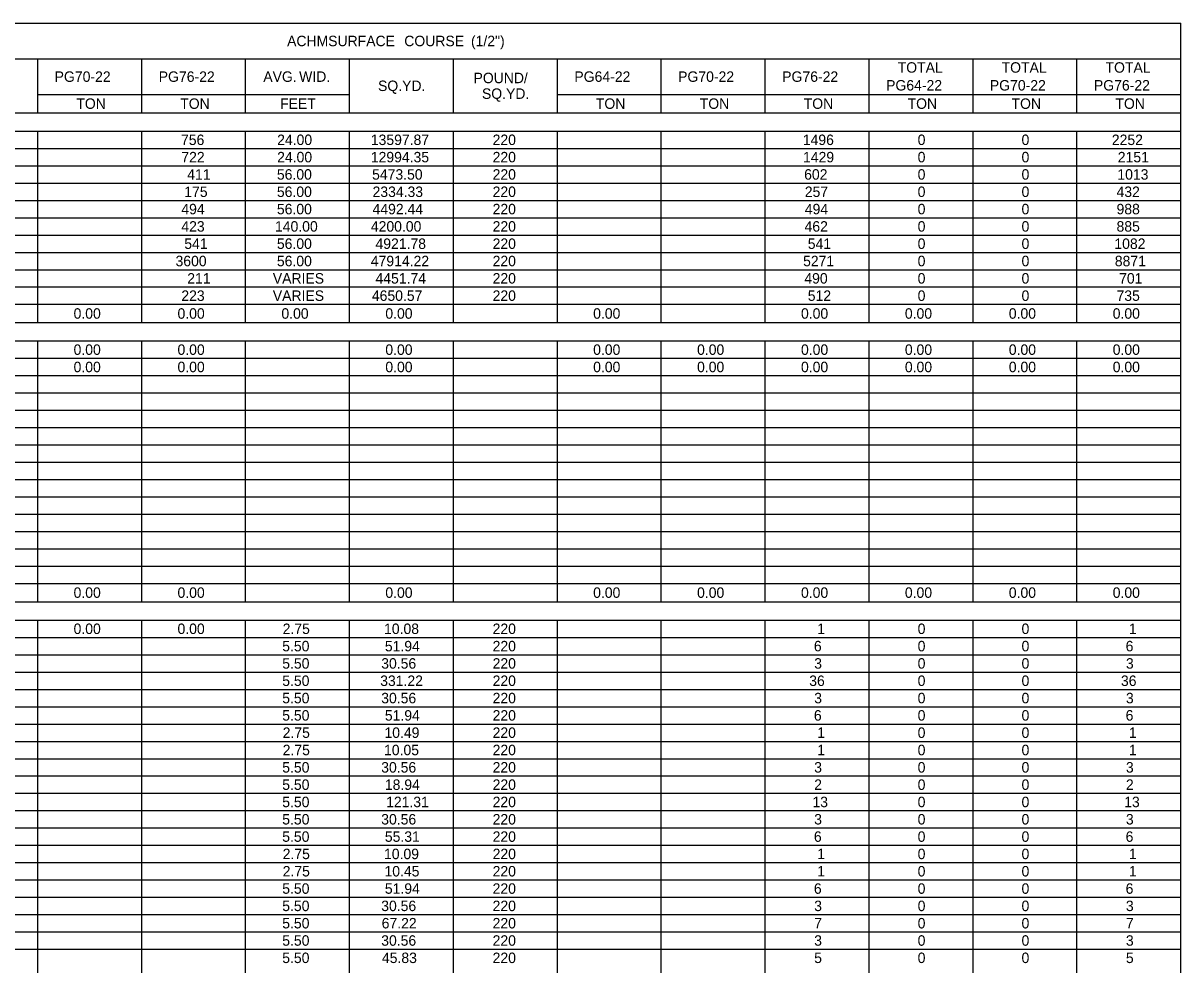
# Model space of a CAD drawing. Extents: x 1226590 to 1228573, y 151304 to 154224.
# Drawn here: x 1228019 to 1228573, y 153764 to 154214 of the extents above; entities that cross this region are included whole.
import ezdxf

# ---------------------------------------------------------------- set-up
doc = ezdxf.new("R2010")
doc.units = 0
doc.layers.add('R_Dimension', color=7, linetype='Continuous')

msp = doc.modelspace()

# ---------------------------------------------------------------- linework, layer by layer
at = {"layer": 'R_Dimension'}
for p, q in [((1226590.27, 154214.43), (1228572.93, 154214.43)), ((1228572.93, 152627.62), (1228572.93, 154214.43)), ((1226981.73, 154197.37), (1228572.93, 154197.37)), ((1228025.96, 154171.53), (1228025.96, 154197.37)), ((1228075.68, 154171.53), (1228075.68, 154197.37)), ((1228125.41, 154171.53), (1228125.41, 154197.37)), ((1228175.13, 154171.53), (1228175.13, 154197.37)), ((1228224.86, 154171.53), (1228224.86, 154197.37)), ((1228274.58, 154171.53), (1228274.58, 154197.37)), ((1228324.31, 154171.53), (1228324.31, 154197.37)), ((1228374.03, 154171.53), (1228374.03, 154197.37)), ((1228423.76, 154171.53), (1228423.76, 154197.37)), ((1228473.48, 154171.53), (1228473.48, 154197.37)), ((1228523.21, 154171.53), (1228523.21, 154197.37)), ((1228025.96, 154180.3), (1228175.13, 154180.3)), ((1228274.58, 154180.3), (1228572.93, 154180.3)), ((1226590.27, 154171.53), (1228572.93, 154171.53)), ((1227926.51, 154171.53), (1228224.86, 154171.53)), ((1228175.13, 154171.53), (1228572.93, 154171.53)), ((1226590.27, 154162.75), (1228572.93, 154162.75)), ((1228025.96, 154071.1), (1228025.96, 154162.75)), ((1228075.68, 154071.1), (1228075.68, 154162.75)), ((1228125.41, 154071.1), (1228125.41, 154162.75)), ((1228175.13, 154071.1), (1228175.13, 154162.75)), ((1228224.86, 154071.1), (1228224.86, 154162.75)), ((1228274.58, 154071.1), (1228274.58, 154162.75)), ((1228324.31, 154071.1), (1228324.31, 154162.75)), ((1228374.03, 154071.1), (1228374.03, 154162.75)), ((1228423.76, 154071.1), (1228423.76, 154162.75)), ((1228473.48, 154071.1), (1228473.48, 154162.75)), ((1228523.21, 154071.1), (1228523.21, 154162.75)), ((1226590.27, 154154.47), (1228572.93, 154154.47)), ((1226590.27, 154146.18), (1228572.93, 154146.18)), ((1226590.27, 154137.89), (1228572.93, 154137.89)), ((1226590.27, 154129.6), (1228572.93, 154129.6)), ((1226590.27, 154121.32), (1228572.93, 154121.32)), ((1226590.27, 154113.03), (1228572.93, 154113.03)), ((1226590.27, 154104.74), (1228572.93, 154104.74)), ((1226590.27, 154096.45), (1228572.93, 154096.45)), ((1226590.27, 154088.17), (1228572.93, 154088.17)), ((1226590.27, 154079.88), (1228572.93, 154079.88)), ((1226590.27, 154071.1), (1228572.93, 154071.1)), ((1226590.27, 154062.33), (1228572.93, 154062.33)), ((1228025.96, 153937.53), (1228025.96, 154062.33)), ((1228075.68, 153937.53), (1228075.68, 154062.33)), ((1228125.41, 153937.53), (1228125.41, 154062.33)), ((1228175.13, 153937.53), (1228175.13, 154062.33)), ((1228224.86, 153937.53), (1228224.86, 154062.33)), ((1228274.58, 153937.53), (1228274.58, 154062.33)), ((1228324.31, 153937.53), (1228324.31, 154062.33)), ((1228374.03, 153937.53), (1228374.03, 154062.33)), ((1228423.76, 153937.53), (1228423.76, 154062.33)), ((1228473.48, 153937.53), (1228473.48, 154062.33)), ((1228523.21, 153937.53), (1228523.21, 154062.33)), ((1226590.27, 154054.04), (1228572.93, 154054.04)), ((1226590.27, 154045.75), (1228572.93, 154045.75)), ((1226590.27, 154037.47), (1228572.93, 154037.47)), ((1226590.27, 154029.18), (1228572.93, 154029.18)), ((1226590.27, 154020.89), (1228572.93, 154020.89)), ((1226590.27, 154012.6), (1228572.93, 154012.6)), ((1226590.27, 154004.32), (1228572.93, 154004.32)), ((1226590.27, 153996.03), (1228572.93, 153996.03)), ((1226590.27, 153987.74), (1228572.93, 153987.74)), ((1226590.27, 153979.45), (1228572.93, 153979.45)), ((1226590.27, 153971.17), (1228572.93, 153971.17)), ((1226590.27, 153962.88), (1228572.93, 153962.88)), ((1226590.27, 153954.59), (1228572.93, 153954.59)), ((1226590.27, 153946.3), (1228572.93, 153946.3)), ((1226590.27, 153937.53), (1228572.93, 153937.53)), ((1226590.27, 153928.75), (1228572.93, 153928.75)), ((1228025.96, 153323.28), (1228025.96, 153928.75)), ((1228075.68, 153323.28), (1228075.68, 153928.75)), ((1228125.41, 153323.28), (1228125.41, 153928.75)), ((1228175.13, 153323.28), (1228175.13, 153928.75)), ((1228224.86, 153323.28), (1228224.86, 153928.75)), ((1228274.58, 153323.28), (1228274.58, 153928.75)), ((1228324.31, 153323.28), (1228324.31, 153928.75)), ((1228374.03, 153323.28), (1228374.03, 153928.75)), ((1228423.76, 153323.28), (1228423.76, 153928.75)), ((1228473.48, 153323.28), (1228473.48, 153928.75)), ((1228523.21, 153323.28), (1228523.21, 153928.75)), ((1226590.27, 153920.47), (1228572.93, 153920.47)), ((1226590.27, 153912.18), (1228572.93, 153912.18)), ((1226590.27, 153903.89), (1228572.93, 153903.89)), ((1226590.27, 153895.6), (1228572.93, 153895.6)), ((1226590.27, 153887.32), (1228572.93, 153887.32)), ((1226590.27, 153879.03), (1228572.93, 153879.03)), ((1226590.27, 153870.74), (1228572.93, 153870.74)), ((1226590.27, 153862.45), (1228572.93, 153862.45)), ((1226590.27, 153854.17), (1228572.93, 153854.17)), ((1226590.27, 153845.88), (1228572.93, 153845.88)), ((1226590.27, 153837.59), (1228572.93, 153837.59)), ((1226590.27, 153829.3), (1228572.93, 153829.3)), ((1226590.27, 153821.02), (1228572.93, 153821.02)), ((1226590.27, 153812.73), (1228572.93, 153812.73)), ((1226590.27, 153804.44), (1228572.93, 153804.44)), ((1226590.27, 153796.15), (1228572.93, 153796.15)), ((1226590.27, 153787.87), (1228572.93, 153787.87)), ((1226590.27, 153779.58), (1228572.93, 153779.58)), ((1226590.27, 153771.29), (1228572.93, 153771.29))]:
    msp.add_line(p, q, dxfattribs=at)

# ---------------------------------------------------------------- texts
for s, p in [(' (1/2")', (1228231.39, 154203.4)), ('ACHM', (1228145.25, 154203.4)), (' SURFACE', (1228163.05, 154203.4)), (' COURSE', (1228199.46, 154203.4)), ('TOTAL', (1228437.44, 154190.72)), ('TOTAL', (1228487.16, 154190.72)), ('TOTAL', (1228536.89, 154190.72)), ('PG', (1228034.01, 154186.34)), (' 70-22', (1228041.84, 154186.34)), ('PG', (1228083.81, 154186.34)), (' 76-22', (1228091.65, 154186.34)), ('AVG.', (1228133.87, 154186.34)), (' WID.', (1228149.15, 154186.34)), ('SQ.YD.', (1228188.77, 154181.95)), ('POUND', (1228234.46, 154185.7)), (' /', (1228256.71, 154185.7)), ('PG', (1228282.71, 154186.34)), (' 64-22', (1228290.55, 154186.34)), ('PG', (1228332.36, 154186.34)), (' 70-22', (1228340.19, 154186.34)), ('PG', (1228382.16, 154186.34)), (' 76-22', (1228390, 154186.34)), ('PG', (1228431.89, 154182.19)), (' 64-22', (1228439.72, 154182.19)), ('PG', (1228481.53, 154182.19)), (' 70-22', (1228489.37, 154182.19)), ('PG', (1228531.34, 154182.19)), (' 76-22', (1228539.17, 154182.19)), ('SQ.YD.', (1228238.5, 154178.2)), ('TON', (1228044.38, 154173.42)), ('TON', (1228094.11, 154173.42)), ('FEET', (1228141.9, 154173.42)), ('TON', (1228293.01, 154173.42)), ('TON', (1228342.73, 154173.42)), ('TON', (1228392.46, 154173.42)), ('TON', (1228442.18, 154173.42)), ('TON', (1228491.91, 154173.42)), ('TON', (1228541.63, 154173.42)), ('756', (1228094.5, 154156.11)), ('24.00', (1228140.49, 154156.11)), ('13597.87', (1228185.31, 154156.11)), ('220', (1228243.6, 154156.11)), ('1496', (1228392.03, 154156.11)), ('0', (1228446.99, 154156.11)), ('0', (1228496.71, 154156.11)), ('2252', (1228539.92, 154156.11)), ('722', (1228094.64, 154147.82)), ('24.00', (1228140.49, 154147.82)), ('12994.35', (1228185.31, 154147.82)), ('220', (1228243.6, 154147.82)), ('1429', (1228392.14, 154147.82)), ('0', (1228446.99, 154147.82)), ('0', (1228496.71, 154147.82)), ('2151', (1228542.76, 154147.82)), ('411', (1228097.47, 154139.54)), ('56.00', (1228140.37, 154139.54)), ('5473.50', (1228185.92, 154139.54)), ('220', (1228243.6, 154139.54)), ('602', (1228392.67, 154139.54)), ('0', (1228446.99, 154139.54)), ('0', (1228496.71, 154139.54)), ('1013', (1228542.56, 154139.54)), ('175', (1228096.06, 154131.25)), ('56.00', (1228140.37, 154131.25)), ('2334.33', (1228186.14, 154131.25)), ('220', (1228243.6, 154131.25)), ('257', (1228392.99, 154131.25)), ('0', (1228446.99, 154131.25)), ('0', (1228496.71, 154131.25)), ('432', (1228542.16, 154131.25)), ('494', (1228094.64, 154122.96)), ('56.00', (1228140.37, 154122.96)), ('4492.44', (1228186.14, 154122.96)), ('220', (1228243.6, 154122.96)), ('494', (1228392.99, 154122.96)), ('0', (1228446.99, 154122.96)), ('0', (1228496.71, 154122.96)), ('988', (1228542.16, 154122.96)), ('423', (1228094.64, 154114.67)), ('140.00', (1228139.46, 154114.67)), ('4200.00', (1228185.33, 154114.67)), ('220', (1228243.6, 154114.67)), ('462', (1228392.87, 154114.67)), ('0', (1228446.99, 154114.67)), ('0', (1228496.71, 154114.67)), ('885', (1228542.16, 154114.67)), ('541', (1228096.06, 154106.39)), ('56.00', (1228140.37, 154106.39)), ('4921.78', (1228187.55, 154106.39)), ('220', (1228243.6, 154106.39)), ('541', (1228394.41, 154106.39)), ('0', (1228446.99, 154106.39)), ('0', (1228496.71, 154106.39)), ('1082', (1228541.14, 154106.39)), ('3600', (1228091.86, 154098.1)), ('56.00', (1228140.37, 154098.1)), ('47914.22', (1228185.31, 154098.1)), ('220', (1228243.6, 154098.1)), ('5271', (1228392.16, 154098.1)), ('0', (1228446.99, 154098.1)), ('0', (1228496.71, 154098.1)), ('8871', (1228541.34, 154098.1)), ('211', (1228097.47, 154089.81)), ('VARIES', (1228138.42, 154089.81)), ('4451.74', (1228187.55, 154089.81)), ('220', (1228243.6, 154089.81)), ('490', (1228392.77, 154089.81)), ('0', (1228446.99, 154089.81)), ('0', (1228496.71, 154089.81)), ('701', (1228543.39, 154089.81)), ('223', (1228094.64, 154081.52)), ('VARIES', (1228138.42, 154081.52)), ('4650.57', (1228185.82, 154081.52)), ('220', (1228243.6, 154081.52)), ('512', (1228394.41, 154081.52)), ('0', (1228446.99, 154081.52)), ('0', (1228496.71, 154081.52)), ('735', (1228542.16, 154081.52)), ('0.00', (1228043.08, 154072.99)), ('0.00', (1228092.81, 154072.99)), ('0.00', (1228142.53, 154072.99)), ('0.00', (1228192.26, 154072.99)), ('0.00', (1228291.71, 154072.99)), ('0.00', (1228391.16, 154072.99)), ('0.00', (1228440.88, 154072.99)), ('0.00', (1228490.61, 154072.99)), ('0.00', (1228540.33, 154072.99)), ('0.00', (1228043.08, 154055.69)), ('0.00', (1228092.81, 154055.69)), ('0.00', (1228192.26, 154055.69)), ('0.00', (1228291.71, 154055.69)), ('0.00', (1228341.43, 154055.69)), ('0.00', (1228391.16, 154055.69)), ('0.00', (1228440.88, 154055.69)), ('0.00', (1228490.61, 154055.69)), ('0.00', (1228540.33, 154055.69)), ('0.00', (1228043.08, 154047.4)), ('0.00', (1228092.81, 154047.4)), ('0.00', (1228192.26, 154047.4)), ('0.00', (1228291.71, 154047.4)), ('0.00', (1228341.43, 154047.4)), ('0.00', (1228391.16, 154047.4)), ('0.00', (1228440.88, 154047.4)), ('0.00', (1228490.61, 154047.4)), ('0.00', (1228540.33, 154047.4)), ('0.00', (1228043.08, 153939.42)), ('0.00', (1228092.81, 153939.42)), ('0.00', (1228192.26, 153939.42)), ('0.00', (1228291.71, 153939.42)), ('0.00', (1228341.43, 153939.42)), ('0.00', (1228391.16, 153939.42)), ('0.00', (1228440.88, 153939.42)), ('0.00', (1228490.61, 153939.42)), ('0.00', (1228540.33, 153939.42)), ('0.00', (1228043.08, 153922.11)), ('0.00', (1228092.81, 153922.11)), ('2.75', (1228143.14, 153922.11)), ('10.08', (1228191.65, 153922.11)), ('220', (1228243.6, 153922.11)), ('1', (1228398.9, 153922.11)), ('0', (1228446.99, 153922.11)), ('0', (1228496.71, 153922.11)), ('1', (1228548.07, 153922.11)), ('5.50', (1228142.93, 153913.82)), ('51.94', (1228192.04, 153913.82)), ('220', (1228243.6, 153913.82)), ('6', (1228397.34, 153913.82)), ('0', (1228446.99, 153913.82)), ('0', (1228496.71, 153913.82)), ('6', (1228546.52, 153913.82)), ('5.50', (1228142.93, 153905.54)), ('30.56', (1228190.29, 153905.54)), ('220', (1228243.6, 153905.54)), ('3', (1228397.48, 153905.54)), ('0', (1228446.99, 153905.54)), ('0', (1228496.71, 153905.54)), ('3', (1228546.65, 153905.54)), ('5.50', (1228142.93, 153897.25)), ('331.22', (1228189.8, 153897.25)), ('220', (1228243.6, 153897.25)), ('36', (1228395.1, 153897.25)), ('0', (1228446.99, 153897.25)), ('0', (1228496.71, 153897.25)), ('36', (1228544.27, 153897.25)), ('5.50', (1228142.93, 153888.96)), ('30.56', (1228190.29, 153888.96)), ('220', (1228243.6, 153888.96)), ('3', (1228397.48, 153888.96)), ('0', (1228446.99, 153888.96)), ('0', (1228496.71, 153888.96)), ('3', (1228546.65, 153888.96)), ('5.50', (1228142.93, 153880.67)), ('51.94', (1228192.04, 153880.67)), ('220', (1228243.6, 153880.67)), ('6', (1228397.34, 153880.67)), ('0', (1228446.99, 153880.67)), ('0', (1228496.71, 153880.67)), ('6', (1228546.52, 153880.67)), ('2.75', (1228143.14, 153872.39)), ('10.49', (1228191.83, 153872.39)), ('220', (1228243.6, 153872.39)), ('1', (1228398.9, 153872.39)), ('0', (1228446.99, 153872.39)), ('0', (1228496.71, 153872.39)), ('1', (1228548.07, 153872.39)), ('2.75', (1228143.14, 153864.1)), ('10.05', (1228191.65, 153864.1)), ('220', (1228243.6, 153864.1)), ('1', (1228398.9, 153864.1)), ('0', (1228446.99, 153864.1)), ('0', (1228496.71, 153864.1)), ('1', (1228548.07, 153864.1)), ('5.50', (1228142.93, 153855.81)), ('30.56', (1228190.29, 153855.81)), ('220', (1228243.6, 153855.81)), ('3', (1228397.48, 153855.81)), ('0', (1228446.99, 153855.81)), ('0', (1228496.71, 153855.81)), ('3', (1228546.65, 153855.81)), ('5.50', (1228142.93, 153847.52)), ('18.94', (1228192.04, 153847.52)), ('220', (1228243.6, 153847.52)), ('2', (1228397.48, 153847.52)), ('0', (1228446.99, 153847.52)), ('0', (1228496.71, 153847.52)), ('2', (1228546.65, 153847.52)), ('5.50', (1228142.93, 153839.24)), ('121.31', (1228192.63, 153839.24)), ('220', (1228243.6, 153839.24)), ('13', (1228396.65, 153839.24)), ('0', (1228446.99, 153839.24)), ('0', (1228496.71, 153839.24)), ('13', (1228545.83, 153839.24)), ('5.50', (1228142.93, 153830.95)), ('30.56', (1228190.29, 153830.95)), ('220', (1228243.6, 153830.95)), ('3', (1228397.48, 153830.95)), ('0', (1228446.99, 153830.95)), ('0', (1228496.71, 153830.95)), ('3', (1228546.65, 153830.95)), ('5.50', (1228142.93, 153822.66)), ('55.31', (1228192.04, 153822.66)), ('220', (1228243.6, 153822.66)), ('6', (1228397.34, 153822.66)), ('0', (1228446.99, 153822.66)), ('0', (1228496.71, 153822.66)), ('6', (1228546.52, 153822.66)), ('2.75', (1228143.14, 153814.37)), ('10.09', (1228191.63, 153814.37)), ('220', (1228243.6, 153814.37)), ('1', (1228398.9, 153814.37)), ('0', (1228446.99, 153814.37)), ('0', (1228496.71, 153814.37)), ('1', (1228548.07, 153814.37)), ('2.75', (1228143.14, 153806.09)), ('10.45', (1228191.85, 153806.09)), ('220', (1228243.6, 153806.09)), ('1', (1228398.9, 153806.09)), ('0', (1228446.99, 153806.09)), ('0', (1228496.71, 153806.09)), ('1', (1228548.07, 153806.09)), ('5.50', (1228142.93, 153797.8)), ('51.94', (1228192.04, 153797.8)), ('220', (1228243.6, 153797.8)), ('6', (1228397.34, 153797.8)), ('0', (1228446.99, 153797.8)), ('0', (1228496.71, 153797.8)), ('6', (1228546.52, 153797.8)), ('5.50', (1228142.93, 153789.51)), ('30.56', (1228190.29, 153789.51)), ('220', (1228243.6, 153789.51)), ('3', (1228397.48, 153789.51)), ('0', (1228446.99, 153789.51)), ('0', (1228496.71, 153789.51)), ('3', (1228546.65, 153789.51)), ('5.50', (1228142.93, 153781.22)), ('67.22', (1228190.51, 153781.22)), ('220', (1228243.6, 153781.22)), ('7', (1228397.48, 153781.22)), ('0', (1228446.99, 153781.22)), ('0', (1228496.71, 153781.22)), ('7', (1228546.65, 153781.22)), ('5.50', (1228142.93, 153772.94)), ('30.56', (1228190.29, 153772.94)), ('220', (1228243.6, 153772.94)), ('3', (1228397.48, 153772.94)), ('0', (1228446.99, 153772.94)), ('0', (1228496.71, 153772.94)), ('3', (1228546.65, 153772.94)), ('5.50', (1228142.93, 153764.65)), ('45.83', (1228190.63, 153764.65)), ('220', (1228243.6, 153764.65)), ('5', (1228397.48, 153764.65)), ('0', (1228446.99, 153764.65)), ('0', (1228496.71, 153764.65)), ('5', (1228546.65, 153764.65))]:
    msp.add_text(s, height=5, dxfattribs=at).set_placement(p)

doc.saveas('drawing.dxf')
